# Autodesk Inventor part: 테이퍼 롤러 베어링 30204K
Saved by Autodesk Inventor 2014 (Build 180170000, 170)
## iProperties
Created: 2026-05
Part Number: 테이퍼 롤러 베어링 30204K
Material: 강철, 연강
Document SubType Name: Modeling
Designer: dg
Density: 7.86 g/cm^3
Appearance: 강철
Mass: 95.5271 g
Surface Area: 86.5355 cm^2
Volume: 12.1536 cm^3
Author: jhkim
Description: 테이퍼 롤러 베어링
Creation Date: 2026-04-23
Sending System: Autodesk Inventor 2027
Preprocessor: ST-DEVELOPER v20.1
Author: dg
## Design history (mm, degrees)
node "테이퍼 롤러 베어링 30204K1"
body "Solid1"
node "Solid1_1"
node "기준1"
node "기준2"
